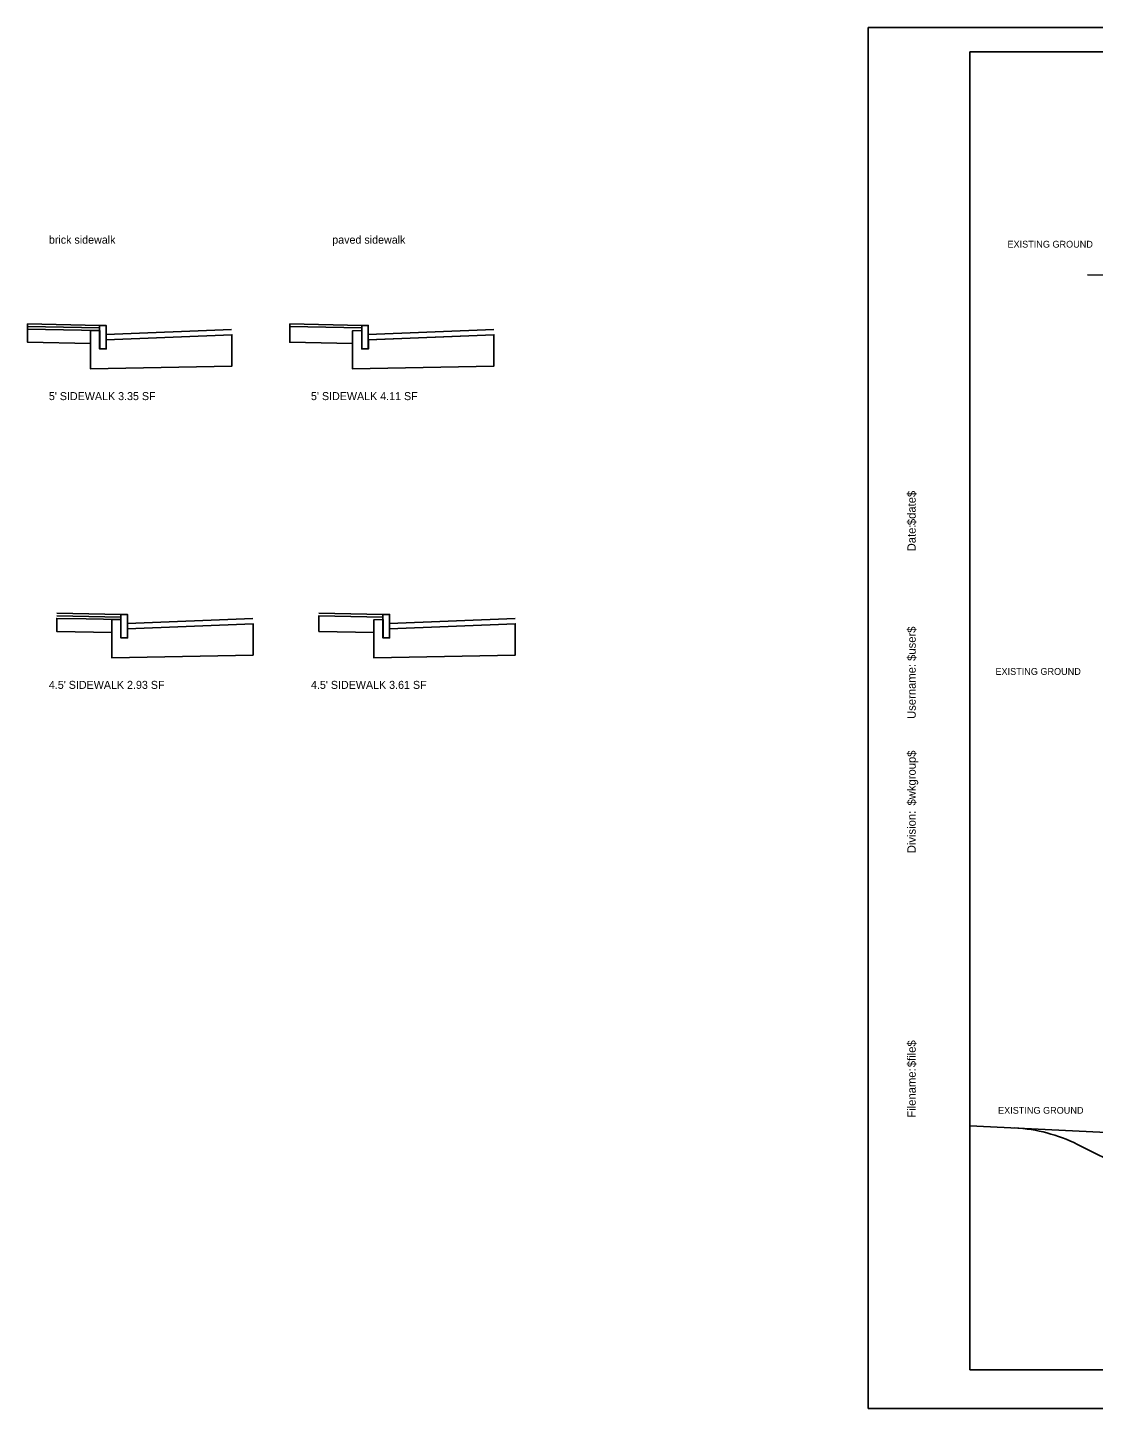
# Model space of a CAD drawing. Extents: x -60 to 130, y -2 to 86.
# Drawn here: x -60.1 to 7.9, y -2.4 to 85.6 of the extents above; entities that cross this region are included whole.
import ezdxf

# ---------------------------------------------------------------- set-up
doc = ezdxf.new("R2010")
doc.units = 0
for name, color, linetype in [('ANNOTATION', 7, 'Continuous'), ('BORDER', 7, 'Continuous'), ('D_Roadway_FinishedGrade', 7, 'Continuous'), ('junk gravel', 7, 'Continuous'), ('PLOT BOUNDARY', 7, 'Continuous'), ('S_Roadway_Centerline', 7, 'Continuous')]:
    doc.layers.add(name, color=color, linetype=linetype)

msp = doc.modelspace()

# ---------------------------------------------------------------- linework, layer by layer
at = {"layer": 'BORDER'}
for p, q in [((128, 84), (0, 84)), ((0, 84), (0, 0)), ((0, 0), (128, 0))]:
    msp.add_line(p, q, dxfattribs=at)
at = {"layer": 'D_Roadway_FinishedGrade'}
msp.add_line((10.919, 12.345), (6.849, 14.379), dxfattribs=at)
msp.add_arc((2.377, 5.435), 10, 63.43495, 87.2073, dxfattribs=at)
at = {"layer": 'junk gravel'}
for p, q in [((-60.059, 66.668), (-55.471, 66.576)), ((-60.059, 66.668), (-60.059, 66.501)), ((-55.471, 66.409), (-60.059, 66.501)), ((-60.059, 66.501), (-60.059, 65.501)), ((-55.471, 66.576), (-55.471, 66.409)), ((-47.054, 66.313), (-55.054, 65.993)), ((-43.353, 66.668), (-38.765, 66.576)), ((-43.353, 66.668), (-43.353, 66.501)), ((-38.765, 66.409), (-43.353, 66.501)), ((-43.353, 66.501), (-43.353, 65.501)), ((-38.765, 66.576), (-38.765, 66.409)), ((-30.348, 66.313), (-38.348, 65.993)), ((-60.059, 65.501), (-56.048, 65.421)), ((-56.054, 65.421), (-56.054, 63.799)), ((-47.041, 65.98), (-55.054, 65.659)), ((-43.353, 65.501), (-39.342, 65.421)), ((-39.348, 65.421), (-39.348, 63.799)), ((-30.335, 65.98), (-38.348, 65.659)), ((-56.054, 63.799), (-47.048, 63.979)), ((-39.348, 63.799), (-30.342, 63.979)), ((-58.197, 48.236), (-54.114, 48.155)), ((-54.114, 47.988), (-58.197, 48.07)), ((-54.114, 48.155), (-54.114, 47.988)), ((-45.697, 47.891), (-53.697, 47.571)), ((-45.684, 47.558), (-53.697, 47.238)), ((-41.491, 48.236), (-37.408, 48.155)), ((-37.408, 47.988), (-41.491, 48.07)), ((-37.408, 48.155), (-37.408, 47.988)), ((-28.991, 47.891), (-36.991, 47.571)), ((-28.978, 47.558), (-36.991, 47.238))]:
    msp.add_line(p, q, dxfattribs=at)
for points in [[(-55.471, 66.243), (-55.471, 66.243), (-60.059, 66.335), (-60.059, 65.501), (-56.048, 65.421), (-56.048, 66.232), (-56.047, 66.232)], [(-55.471, 66.576), (-55.471, 65.076), (-55.054, 65.076), (-55.054, 66.576)], [(-38.765, 66.576), (-38.765, 65.076), (-38.348, 65.076), (-38.348, 66.576)], [(-54.114, 47.822), (-54.114, 47.821), (-56.334, 47.866), (-58.197, 47.903), (-58.197, 47.07), (-54.69, 46.999), (-54.69, 47.81), (-54.69, 47.81)], [(-54.114, 48.155), (-54.114, 46.655), (-53.697, 46.655), (-53.697, 48.155)], [(-37.408, 48.155), (-37.408, 46.655), (-36.991, 46.655), (-36.991, 48.155)]]:
    msp.add_lwpolyline(points, close=True, dxfattribs=at)
for points in [[(-55.048, 65.66), (-55.048, 65.077), (-55.464, 65.077), (-55.464, 66.244), (-56.047, 66.232), (-56.048, 66.232), (-56.048, 63.799), (-47.041, 63.98), (-47.041, 65.98), (-55.048, 65.66)], [(-38.765, 66.243), (-38.765, 66.409), (-38.765, 66.409), (-43.353, 66.501), (-43.353, 65.501), (-39.342, 65.421), (-39.342, 66.232), (-39.341, 66.232), (-38.765, 66.243)], [(-38.342, 65.66), (-38.342, 65.077), (-38.758, 65.077), (-38.758, 66.244), (-39.341, 66.232), (-39.342, 66.232), (-39.342, 63.799), (-30.335, 63.98), (-30.335, 65.98), (-38.342, 65.66)], [(-53.69, 47.238), (-53.69, 46.655), (-54.107, 46.655), (-54.107, 47.822), (-54.69, 47.81), (-54.69, 47.81), (-54.69, 45.378), (-45.684, 45.558), (-45.684, 47.558), (-53.69, 47.238)], [(-37.408, 47.822), (-37.408, 47.988), (-37.408, 47.988), (-41.491, 48.07), (-41.491, 47.07), (-37.984, 46.999), (-37.984, 47.81), (-37.984, 47.81), (-37.408, 47.822)], [(-36.984, 47.238), (-36.984, 46.655), (-37.401, 46.655), (-37.401, 47.822), (-37.984, 47.81), (-37.984, 47.81), (-37.984, 45.378), (-28.978, 45.558), (-28.978, 47.558), (-36.984, 47.238)]]:
    msp.add_lwpolyline(points, dxfattribs=at)
at = {"layer": 'PLOT BOUNDARY'}
msp.add_lwpolyline([(-6.475, -2.447), (129.525, -2.447), (129.525, 85.553), (-6.475, 85.553)], close=True, dxfattribs=at)
at = {"layer": 'S_Roadway_Centerline'}
for points in [[(20.088, 71.514), (9.636, 69.766), (7.494, 69.789)], [(0, 15.564), (10.906, 15.032), (14.329, 14.462), (17.364, 13.956)]]:
    msp.add_lwpolyline(points, dxfattribs=at)

# ---------------------------------------------------------------- texts
at = {"layer": 'ANNOTATION'}
for p in [(2.396, 71.532), (1.628, 44.301), (1.797, 16.331)]:
    msp.add_text('EXISTING GROUND', height=0.4335, dxfattribs=at).set_placement(p)
at = {"layer": 'BORDER'}
for s, p in [('$date$', (-3.452, 53.844)), ('Date:', (-3.452, 52.173)), ('$user$', (-3.452, 45.193)), ('Username:', (-3.452, 41.494)), ('$wkgroup$', (-3.452, 35.976)), ('Division:', (-3.452, 32.933)), ('$file$', (-3.452, 19.3)), ('Filename:', (-3.452, 16.079))]:
    msp.add_text(s, height=0.5357, rotation=90, dxfattribs=at).set_placement(p)
at = {"layer": 'junk gravel'}
for s, p in [('brick sidewalk', (-58.704, 71.781)), ('paved sidewalk', (-40.642, 71.781)), ("5' SIDEWALK 3.35 SF", (-58.704, 61.812)), ("5' SIDEWALK 4.11 SF", (-41.998, 61.812)), ("4.5' SIDEWALK 2.93 SF", (-58.704, 43.409)), ("4.5' SIDEWALK 3.61 SF", (-41.998, 43.409))]:
    msp.add_text(s, height=0.51, dxfattribs=at).set_placement(p)

doc.saveas('drawing.dxf')
